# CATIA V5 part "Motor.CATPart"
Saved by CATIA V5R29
Part number: Motor
Bounding box of the stored display mesh (mm): x -60 to 60, y -30 to 65, z -67.5 to 60
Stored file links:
  D:\Abhinav\2019\3rd Session\CATIA V5 2019\RESOURCES\CATIA_RESOURCES\Tutorial Files\Tutorials\Tutorials\c12_catia_v5_6r2018_tut\c12_catia_v5_6r2018_tut\c12_catia_v5_6r2018_tut\c12Tut1\Motor.CATPart
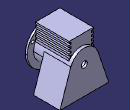
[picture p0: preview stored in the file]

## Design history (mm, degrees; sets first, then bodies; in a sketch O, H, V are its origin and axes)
Body1 (main body)
  Sketch1 on zx-plane, origin (0, 0, 0), H (-1, 0, 0), V (0, 0, 1)
    arc A1 centre (0, 0) radius 35 from (33.1265, 11.2976) to (-33.1265, 11.2976) ccw
    line L1 (-60, -67.5) -> (60, -67.5)
    point P1 (-60, -67.5)
    line L2 (60, -67.5) -> (33.1265, 11.2976)
    line L3 (-60, -67.5) -> (-33.1265, 11.2976)
    point P4 (-33.1265, 11.2976)
    point P5 (-33.1265, 11.2976)
    radius A1 = 35
    length L1 = 120
    distance H L1 = 67.5
    distance P1 V = 60
    horizontal: L1 H
    tangency: L3 A1, L2 A1
    coincidence: L3 P5, P4 A1, P4 P5
  Pad1: profile Sketch1, direction (0, 1, 0), length 65
  Sketch2 on face of Pad1, origin (0, 65, 0), H (-1, 0, 0), V (0, 0, 1)
    circle A1 centre (0, 0) radius 35
    reference projected arc E1 centre (0, 0) radius 35 from (33.1265, 11.2976) to (-33.1265, 11.2976) ccw from edge [face of Pad1 from Sketch1.A1 | end face of Pad1]
    reference projected arc E2 centre (0, 0) radius 35 from (33.1265, 11.2976) to (-33.1265, 11.2976) ccw from edge [face of Pad1 from Sketch1.A1 | end face of Pad1]
    coincidence: A1 E1
    concentricity: A1 E2
  Pad2: profile Sketch2, direction (0, -1, 0), length 90
  Sketch3 on xy-plane, origin (0, 0, 0), H (1, 0, 0), V (0, 1, 0)
    line L1 (-30, 57.5) -> (30, 57.5)
    line L2 (30, 57.5) -> (30, -25)
    line L3 (30, -25) -> (-30, -25)
    line L4 (-30, -25) -> (-30, 57.5)
    reference projected line E1 (-35, -25) -> (35, -25) from edge of Pad2
    reference projected line E2 (33.1265, 65) -> (-33.1265, 65) from edge of Pad1
    length L1 = 60
    distance L4 V = 30
    distance E2 L1 = 7.5
    horizontal: L1 H, L3 H
    vertical: L2 V, L4 V
    coincidence: E1 L3
  Pad3: profile Sketch3, direction (0, 0, 1), length 60
  Sketch4 on face of Pad2, origin (0, -25, 0), H (1, 0, 0), V (0, 0, 1)
    circle A1 centre (0, 0) radius 50
    radius A1 = 50
  Pad4: profile Sketch4, direction (0, -1, 0), length 5
  Sketch5 on face of Pad3, origin (0, 57.5, 0), H (-1, 0, 0), V (0, 0, 1)
    line L1 (-30, 28.8) -> (-25, 28.8)
    line L2 (-25, 28.8) -> (-25, 24.3)
    line L3 (-25, 24.3) -> (-30, 24.3)
    line L4 (-30, 24.3) -> (-30, 28.8)
    reference projected line E1 (-30, 0) -> (-30, 60) from edge of Pad3
    length L1 = 5
    length L2 = 4.5
    distance L3 H = 24.3
    horizontal: L1 H, L3 H
    vertical: L2 V, L4 V
    coincidence: L4 E1
  Pocket1: profile Sketch5, direction (0, -1, 0), up to face of Pad3
  RectPattern1: of Pocket1, direction 1 instances 4, spacing 9, along edge of Pad3 reversed, direction 2 instances 2, spacing 55, along edge of Pad3
  Sketch6 on face of Pad4, origin (0, -30, 0), H (1, 0, 0), V (0, 0, 1)
    circle A1 centre (0, -42.5) radius 3.75
    point P1 (0, -42.5)
    radius A1 = 3.75
    distance P1 H = 42.5
    coincidence: P1 V
  Pocket2: profile Sketch6, direction (0, 1, 0), length 12.7
  CircPattern1: of Pocket2, instances 3, angular step 120, axis from face
  Sketch7 on face of Pad4, origin (0, -30, 0), H (1, 0, 0), V (0, 0, 1)
    circle A1 centre (0, 0) radius 30
    circle A2 centre (0, 0) radius 7.5
    radius A1 = 30
    radius A2 = 7.5
  MultiPocket1: profile Sketch7, domains (length 254; length 90)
